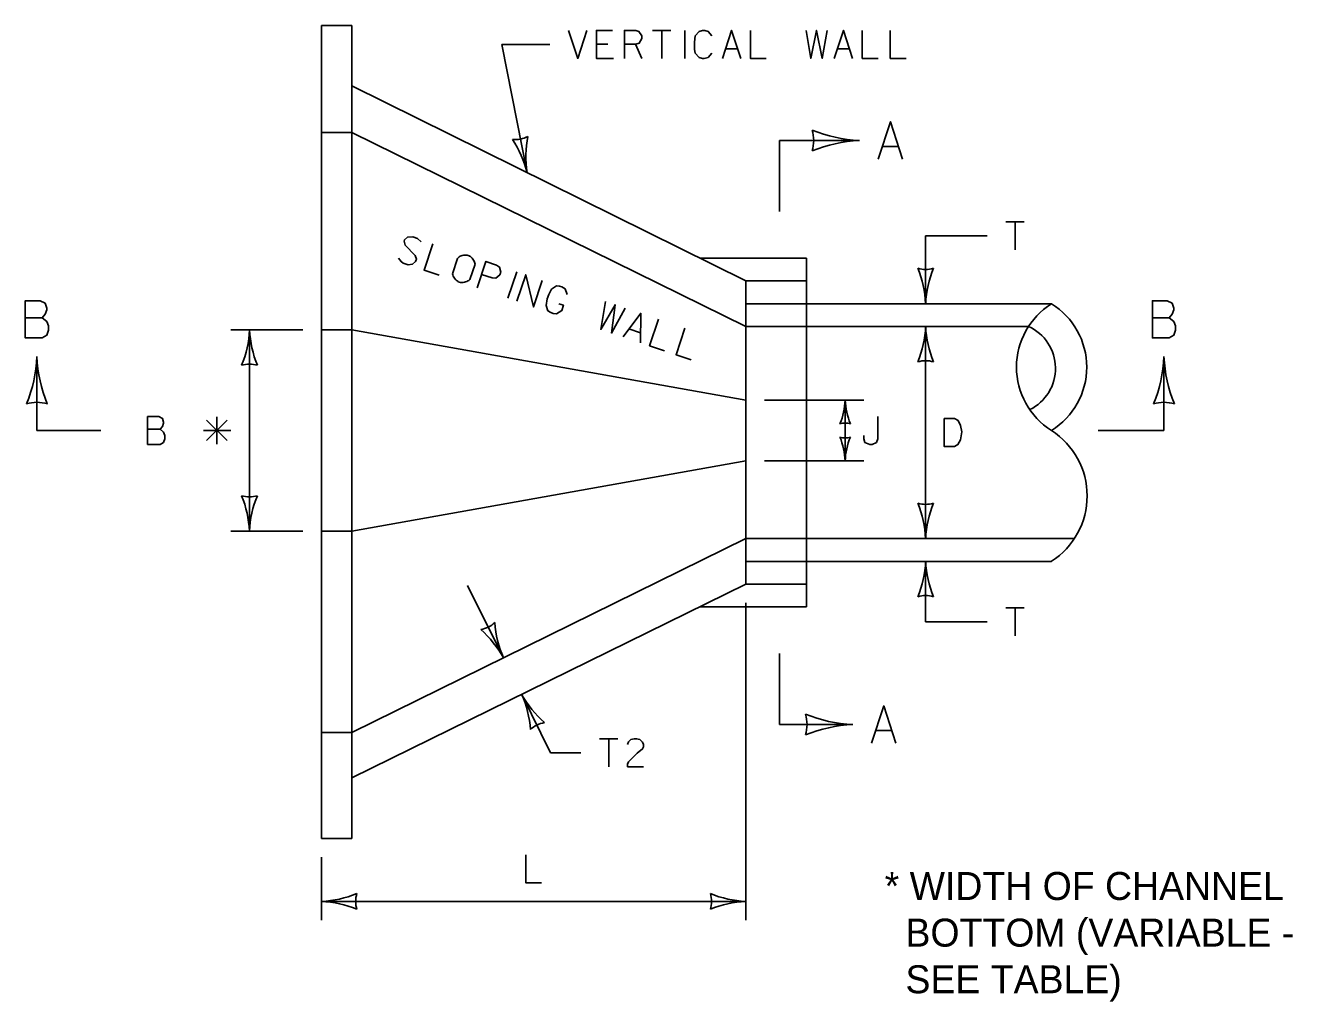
# Model space of a CAD drawing. Extents: x 49991.4 to 50043, y 49987.6 to 50011.4.
# Drawn here: x 50035.373 to 50038.09, y 49993.826 to 49995.92 of the extents above; entities that cross this region are included whole.
import ezdxf

# ---------------------------------------------------------------- set-up
doc = ezdxf.new("R2010")
doc.units = 0
for name, color, linetype in [('Level 1', 7, 'Continuous'), ('Level 2', 7, 'Continuous'), ('Level 3', 7, 'Continuous'), ('Level 4', 7, 'Continuous'), ('Level 6', 7, 'Continuous')]:
    doc.layers.add(name, color=color, linetype=linetype)

msp = doc.modelspace()

# ---------------------------------------------------------------- linework, layer by layer
at = {"layer": 'Level 1'}
for p, q in [((50036.073, 49995.9197), (50036.008, 49995.9197)), ((50036.008, 49995.9197), (50036.008, 49994.1757)), ((50036.073, 49994.1757), (50036.073, 49995.9197)), ((50036.918, 49995.3715), (50036.073, 49995.7897)), ((50036.073, 49995.6898), (50036.008, 49995.6898)), ((50036.918, 49995.274), (50036.073, 49995.6898)), ((50037.048, 49995.4203), (50036.8194, 49995.4203)), ((50037.048, 49995.4203), (50037.048, 49994.6728)), ((50036.918, 49994.7215), (50036.918, 49995.3715)), ((50037.5732, 49995.3228), (50036.918, 49995.3228)), ((50036.073, 49995.2668), (50036.008, 49995.2668)), ((50036.073, 49995.2668), (50036.918, 49995.1159)), ((50036.073, 49994.835), (50036.918, 49994.9859)), ((50036.073, 49994.835), (50036.008, 49994.835)), ((50036.918, 49994.819), (50036.073, 49994.4032)), ((50037.5732, 49994.7703), (50036.918, 49994.7703)), ((50036.918, 49994.7215), (50036.073, 49994.3057)), ((50037.048, 49994.6728), (50036.8191, 49994.6728)), ((50036.073, 49994.4032), (50036.008, 49994.4032)), ((50036.008, 49994.1757), (50036.073, 49994.1757))]:
    msp.add_line(p, q, dxfattribs=at)
for centre, radius, start, end in [((50037.6592, 49995.1868), 0.1609, 122.3335, 237.6665), ((50037.489, 49995.1868), 0.1599, 301.772, 58.228), ((50037.4831, 49995.1842), 0.0988, 296.2298, 65.513), ((50037.4831, 49994.9106), 0.1667, 302.7325, 57.2885)]:
    msp.add_arc(centre, radius, start, end, dxfattribs=at)
at = {"layer": 'Level 2'}
for p, q in [((50036.7177, 49995.9087), (50036.757, 49995.9087)), ((50036.7376, 49995.9087), (50036.7376, 49995.8487)), ((50036.7874, 49995.8487), (50036.7874, 49995.9087)), ((50036.6223, 49995.879), (50036.5977, 49995.879)), ((50036.6951, 49995.8487), (50036.6814, 49995.8794)), ((50036.8744, 49995.869), (50036.9003, 49995.869)), ((50037.1144, 49995.869), (50037.1403, 49995.869)), ((50037.2103, 49995.6599), (50037.2449, 49995.6599)), ((50037.4753, 49995.498), (50037.5146, 49995.498)), ((50037.4952, 49995.498), (50037.4952, 49995.438)), ((50036.2998, 49995.4199), (50036.2888, 49995.3872)), ((50036.3206, 49995.4269), (50036.325, 49995.4254)), ((50036.3374, 49995.4073), (50036.3264, 49995.3746)), ((50036.4079, 49995.3344), (50036.4269, 49995.3912)), ((50036.3015, 49995.37), (50036.306, 49995.3685)), ((50036.6674, 49995.2688), (50036.6921, 49995.2605)), ((50035.7619, 49995.0294), (50035.8063, 49995.0729)), ((50035.8063, 49995.0294), (50035.7619, 49995.0729)), ((50035.7841, 49995.0219), (50035.7841, 49995.0804)), ((50035.7553, 49995.0512), (50035.8138, 49995.0512)), ((50037.4753, 49994.6709), (50037.5146, 49994.6709)), ((50037.4952, 49994.6709), (50037.4952, 49994.6109)), ((50037.1961, 49994.4074), (50037.2307, 49994.4074)), ((50036.6045, 49994.3899), (50036.6438, 49994.3899)), ((50036.6244, 49994.3899), (50036.6244, 49994.3299))]:
    msp.add_line(p, q, dxfattribs=at)
for points in [[(50036.5377, 49995.9087), (50036.5576, 49995.8487), (50036.577, 49995.9087)], [(50036.6322, 49995.9087), (50036.5977, 49995.9087), (50036.5977, 49995.8487), (50036.6346, 49995.8487)], [(50036.6577, 49995.8487), (50036.6577, 49995.9087), (50036.6818, 49995.9087), (50036.6889, 49995.9064), (50036.6951, 49995.8969), (50036.6951, 49995.8912), (50036.6894, 49995.8818), (50036.6818, 49995.8794), (50036.6577, 49995.8794)], [(50036.8451, 49995.8969), (50036.8375, 49995.9068), (50036.83, 49995.9087), (50036.8248, 49995.9087), (50036.8177, 49995.9068), (50036.8096, 49995.8969), (50036.8077, 49995.8837), (50036.8077, 49995.8766), (50036.8077, 49995.8719), (50036.8082, 49995.8676), (50036.8096, 49995.8601), (50036.8177, 49995.8506), (50036.8248, 49995.8487), (50036.829, 49995.8487), (50036.837, 49995.8506), (50036.8451, 49995.8601)], [(50036.8677, 49995.8487), (50036.8876, 49995.9087), (50036.907, 49995.8487)], [(50036.9277, 49995.9087), (50036.9277, 49995.8487), (50036.9618, 49995.8487)], [(50037.0477, 49995.9087), (50037.0572, 49995.8487), (50037.0695, 49995.9087), (50037.0818, 49995.8487), (50037.0922, 49995.9087)], [(50037.1077, 49995.8487), (50037.1276, 49995.9087), (50037.147, 49995.8487)], [(50037.1677, 49995.9087), (50037.1677, 49995.8487), (50037.2018, 49995.8487)], [(50037.2277, 49995.9087), (50037.2277, 49995.8487), (50037.2618, 49995.8487)], [(50037.2014, 49995.6329), (50037.2279, 49995.7128), (50037.2537, 49995.6329)], [(50036.2216, 49995.4556), (50036.214, 49995.4626), (50036.2037, 49995.4661), (50036.1929, 49995.4652), (50036.1865, 49995.4594), (50036.1856, 49995.4567), (50036.1878, 49995.4485), (50036.2093, 49995.4264), (50036.2116, 49995.4186), (50036.2094, 49995.4134), (50036.203, 49995.4075), (50036.194, 49995.4061), (50036.1832, 49995.4097), (50036.1789, 49995.4131), (50036.1734, 49995.4204)], [(50036.2471, 49995.4515), (50036.228, 49995.3946), (50036.2603, 49995.3838)], [(50036.2998, 49995.4199), (50036.3016, 49995.4216), (50036.3035, 49995.4231), (50036.3056, 49995.4244), (50036.3078, 49995.4254), (50036.3101, 49995.4262), (50036.3125, 49995.4268), (50036.3149, 49995.4271), (50036.3173, 49995.4272), (50036.3198, 49995.427), (50036.3206, 49995.4269)], [(50036.3374, 49995.4073), (50036.337, 49995.4097), (50036.3364, 49995.4121), (50036.3355, 49995.4143), (50036.3344, 49995.4165), (50036.333, 49995.4186), (50036.3315, 49995.4205), (50036.3297, 49995.4222), (50036.3278, 49995.4237), (50036.3257, 49995.425), (50036.325, 49995.4254)], [(50036.3418, 49995.3565), (50036.3609, 49995.4134), (50036.3837, 49995.4057), (50036.3897, 49995.4012), (50036.3925, 49995.3903), (50036.3907, 49995.385), (50036.3823, 49995.3778), (50036.3744, 49995.378), (50036.3516, 49995.3856)], [(50036.2888, 49995.3872), (50036.2895, 49995.3846), (50036.2905, 49995.3821), (50036.2917, 49995.3797), (50036.2932, 49995.3774), (50036.2948, 49995.3753), (50036.2967, 49995.3734), (50036.2988, 49995.3717), (50036.3011, 49995.3702), (50036.3015, 49995.37)], [(50036.4271, 49995.3279), (50036.4462, 49995.3848), (50036.4625, 49995.316), (50036.4816, 49995.3729)], [(50036.3264, 49995.3746), (50036.3243, 49995.3729), (50036.322, 49995.3715), (50036.3196, 49995.3703), (50036.3171, 49995.3694), (50036.3145, 49995.3688), (50036.3118, 49995.3684), (50036.3091, 49995.3683), (50036.3064, 49995.3685), (50036.306, 49995.3685)], [(50036.5347, 49995.3426), (50036.5303, 49995.3546), (50036.5237, 49995.3588), (50036.5183, 49995.3606), (50036.5119, 49995.3608), (50036.5011, 49995.3539), (50036.4953, 49995.3424), (50036.4921, 49995.333), (50036.4899, 49995.3188), (50036.4936, 49995.3076), (50036.4997, 49995.3036), (50036.5046, 49995.3019), (50036.5124, 49995.3013), (50036.5232, 49995.3082), (50036.5269, 49995.3194), (50036.5171, 49995.3227)], [(50035.4091, 49995.2927), (50035.416, 49995.3003), (50035.4192, 49995.3097), (50035.4192, 49995.3129), (50035.416, 49995.3236), (50035.4053, 49995.3292), (50035.3732, 49995.3292), (50035.3732, 49995.2493), (50035.4091, 49995.2493), (50035.4192, 49995.255), (50035.4229, 49995.2657), (50035.4229, 49995.2751), (50035.4192, 49995.2846), (50035.4091, 49995.2927), (50035.3732, 49995.2927)], [(50036.6169, 49995.3276), (50036.6068, 49995.2677), (50036.6375, 49995.3207), (50036.6301, 49995.2599), (50036.659, 49995.3134)], [(50037.8255, 49995.2927), (50037.8324, 49995.3003), (50037.8356, 49995.3097), (50037.8356, 49995.3129), (50037.8324, 49995.3236), (50037.8217, 49995.3292), (50037.7896, 49995.3292), (50037.7896, 49995.2493), (50037.8255, 49995.2493), (50037.8356, 49995.255), (50037.8393, 49995.2657), (50037.8393, 49995.2751), (50037.8356, 49995.2846), (50037.8255, 49995.2927), (50037.7896, 49995.2927)], [(50036.6547, 49995.2516), (50036.6926, 49995.3022), (50036.6919, 49995.2391)], [(50036.7307, 49995.2894), (50036.7116, 49995.2325), (50036.7438, 49995.2217)], [(50036.7875, 49995.2703), (50036.7685, 49995.2135), (50036.8007, 49995.2026)], [(50035.6622, 49995.0535), (50035.6674, 49995.0592), (50035.6698, 49995.0663), (50035.6698, 49995.0686), (50035.6674, 49995.0767), (50035.6594, 49995.0809), (50035.6353, 49995.0809), (50035.6353, 49995.0209), (50035.6622, 49995.0209), (50035.6698, 49995.0252), (50035.6726, 49995.0332), (50035.6726, 49995.0403), (50035.6698, 49995.0474), (50035.6622, 49995.0535), (50035.6353, 49995.0535)], [(50037.2007, 49995.0809), (50037.2007, 49995.0332), (50037.1979, 49995.0252), (50037.1889, 49995.0209), (50037.1837, 49995.0209), (50037.1733, 49995.0252), (50037.1709, 49995.0327), (50037.1709, 49995.0403)], [(50037.3435, 49995.0765), (50037.3653, 49995.0765), (50037.3733, 49995.0723), (50037.3785, 49995.0619), (50037.3809, 49995.0482), (50037.378, 49995.0312), (50037.3728, 49995.0208), (50037.3653, 49995.0165), (50037.3435, 49995.0165), (50037.3435, 49995.0765)], [(50037.1872, 49994.3803), (50037.2137, 49994.4602), (50037.2395, 49994.3803)], [(50036.6645, 49994.3776), (50036.6664, 49994.3833), (50036.6716, 49994.388), (50036.6787, 49994.3899), (50036.6839, 49994.3899), (50036.691, 49994.388), (50036.6962, 49994.3828), (50036.6986, 49994.3776), (50036.6986, 49994.3724), (50036.6967, 49994.3682), (50036.6849, 49994.3592), (50036.6664, 49994.3403), (50036.6645, 49994.3356), (50036.6645, 49994.3299), (50036.6986, 49994.3299)], [(50036.446, 49994.141), (50036.446, 49994.081), (50036.4801, 49994.081)]]:
    msp.add_lwpolyline(points, dxfattribs=at)
at = {"layer": 'Level 3'}
for p, q in [((50036.3945, 49995.8787), (50036.4977, 49995.8787)), ((50036.4489, 49995.6037), (50036.3945, 49995.8787)), ((50037.3035, 49995.3228), (50037.3035, 49995.468)), ((50037.3035, 49995.468), (50037.4353, 49995.468)), ((50037.3035, 49995.274), (50037.3035, 49994.819)), ((50035.968, 49995.2668), (50035.8138, 49995.2668)), ((50035.8538, 49995.2668), (50035.8538, 49994.835)), ((50036.958, 49995.1159), (50037.1709, 49995.1159)), ((50037.1309, 49995.1159), (50037.1309, 49994.9859)), ((50036.958, 49994.9859), (50037.1709, 49994.9859)), ((50035.968, 49994.835), (50035.8138, 49994.835)), ((50037.3035, 49994.7703), (50037.3035, 49994.6409)), ((50036.3212, 49994.7187), (50036.3984, 49994.5633)), ((50036.918, 49994.6815), (50036.918, 49994.001)), ((50037.3035, 49994.6409), (50037.4353, 49994.6409)), ((50036.4374, 49994.485), (50036.4995, 49994.3599)), ((50036.4995, 49994.3599), (50036.5645, 49994.3599)), ((50036.008, 49994.1357), (50036.008, 49994.001)), ((50036.008, 49994.041), (50036.918, 49994.041))]:
    msp.add_line(p, q, dxfattribs=at)
for centre, radius, start, end in [((50036.4241, 49995.7295), 0.0548, 263.3245, 299.0469), ((50036.6686, 49995.6378), 0.2223, 168.6417, 188.8252), ((50037.1737, 49995.969), 0.2964, 247.456, 267.6395), ((50036.9905, 49995.6728), 0.073, 342.1388, 17.8612), ((50036.2229, 49995.5473), 0.233, 14.013, 33.2629), ((50037.1768, 49995.3625), 0.3107, 92.8273, 112.0772), ((50037.3035, 49995.451), 0.0548, 252.1388, 287.8612), ((50037.0708, 49995.3113), 0.233, 2.8273, 22.0772), ((50037.5257, 49995.3137), 0.2223, 157.456, 177.6395), ((50037.0814, 49995.2832), 0.2223, 337.456, 357.6395), ((50037.5363, 49995.2855), 0.233, 182.8273, 202.0772), ((50035.6317, 49995.276), 0.2223, 337.456, 357.6395), ((50036.0866, 49995.2783), 0.233, 182.8273, 202.0772), ((50035.1019, 49995.2215), 0.2964, 337.456, 357.6395), ((50035.7083, 49995.2246), 0.3107, 182.8273, 202.0772), ((50035.8538, 49995.1386), 0.0548, 72.1388, 107.8612), ((50037.3035, 49995.1458), 0.0548, 72.1388, 107.8612), ((50037.5183, 49995.2215), 0.2964, 337.456, 357.6395), ((50038.1247, 49995.2246), 0.3107, 182.8273, 202.0772), ((50035.398, 49995.0384), 0.073, 72.1388, 107.8612), ((50036.9829, 49995.122), 0.1482, 337.456, 357.6395), ((50037.2861, 49995.1236), 0.1553, 182.8273, 202.0772), ((50037.8144, 49995.0384), 0.073, 72.1388, 107.8612), ((50037.1309, 49995.0304), 0.0365, 72.1388, 107.8612), ((50037.1309, 49995.0714), 0.0365, 252.1388, 287.8612), ((50036.9758, 49994.9783), 0.1553, 2.8273, 22.0772), ((50037.279, 49994.9798), 0.1482, 157.456, 177.6395), ((50035.8538, 49994.9632), 0.0548, 252.1388, 287.8612), ((50035.6211, 49994.8235), 0.233, 2.8273, 22.0772), ((50036.076, 49994.8259), 0.2223, 157.456, 177.6395), ((50037.3035, 49994.9472), 0.0548, 252.1388, 287.8612), ((50037.0708, 49994.8075), 0.233, 2.8273, 22.0772), ((50037.5257, 49994.8099), 0.2223, 157.456, 177.6395), ((50037.0814, 49994.7795), 0.2223, 337.456, 357.6395), ((50037.5363, 49994.7818), 0.233, 182.8273, 202.0772), ((50037.3035, 49994.6421), 0.0548, 72.1388, 107.8612), ((50036.3414, 49994.6782), 0.0548, 278.5638, 314.2861), ((50036.1952, 49994.4495), 0.233, 29.2523, 48.5021), ((50036.6014, 49994.654), 0.2223, 183.881, 204.0645), ((50036.2344, 49994.3943), 0.2223, 3.8914, 24.0749), ((50036.6406, 49994.5989), 0.233, 209.2627, 228.5126), ((50037.1595, 49994.7165), 0.2964, 247.456, 267.6395), ((50036.9763, 49994.4203), 0.073, 342.1388, 17.8612), ((50036.4944, 49994.3702), 0.0548, 98.5742, 134.2966), ((50037.1626, 49994.11), 0.3107, 92.8273, 112.0772), ((50035.9966, 49994.2737), 0.233, 272.8273, 292.0772), ((50036.1363, 49994.041), 0.0548, 162.1388, 197.8612), ((50036.9272, 49994.2632), 0.2223, 247.456, 267.6395), ((50036.7898, 49994.041), 0.0548, 342.1388, 17.8612), ((50035.9989, 49993.8189), 0.2223, 67.456, 87.6395), ((50036.9295, 49993.8083), 0.233, 92.8273, 112.0772)]:
    msp.add_arc(centre, radius, start, end, dxfattribs=at)
at = {"layer": 'Level 4'}
for p, q in [((50036.918, 49995.3715), (50037.048, 49995.3715)), ((50037.524, 49995.274), (50036.918, 49995.274)), ((50037.6224, 49994.819), (50036.918, 49994.819)), ((50036.918, 49994.7215), (50037.048, 49994.7215))]:
    msp.add_line(p, q, dxfattribs=at)
at = {"layer": 'Level 6'}
for p, q in [((50036.9899, 49995.6728), (50037.1614, 49995.6728)), ((50036.9899, 49995.5203), (50036.9899, 49995.6728)), ((50035.398, 49995.0509), (50035.398, 49995.2093)), ((50037.8144, 49995.0509), (50037.8144, 49995.2093)), ((50035.398, 49995.0509), (50035.5353, 49995.0509)), ((50037.6732, 49995.0509), (50037.8144, 49995.0509)), ((50036.9899, 49994.4203), (50036.9899, 49994.5728)), ((50036.9899, 49994.4203), (50037.1472, 49994.4203))]:
    msp.add_line(p, q, dxfattribs=at)

# ---------------------------------------------------------------- texts
at = {"layer": 'Level 2'}
for s, p in [('* WIDTH OF CHANNEL', (50037.2157, 49994.0441)), ('  BOTTOM (VARIABLE -', (50037.2157, 49993.9441)), ('  SEE TABLE)', (50037.2157, 49993.8441))]:
    msp.add_text(s, height=0.06, dxfattribs=at).set_placement(p)

doc.saveas('drawing.dxf')
